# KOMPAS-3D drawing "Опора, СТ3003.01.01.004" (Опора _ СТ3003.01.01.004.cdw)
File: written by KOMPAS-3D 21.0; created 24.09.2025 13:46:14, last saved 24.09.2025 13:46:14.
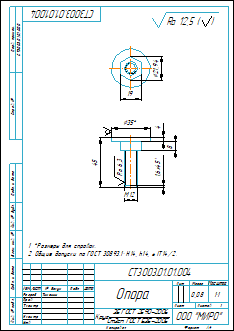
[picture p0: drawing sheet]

Sheet 1: A4, portrait

Document properties: Полное имя файла: C:\Users\1\Yandex.Disk\Документы\Новая папка\Стапель №2\Стапель _ СТ3003.00.00.000\Опора _ СТ3003.01.00.000\2D\Кронштейн _ СТ3003.01.01.000\Опора _ СТ3003.01.01.004.cdw; Знак неуказанной шероховатости: 4; Параметр неуказанной шероховатости: Ra 12,5; Масса: 0.078797

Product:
- Part/product: Опора  | designation СТ3003.01.01.004
    Материал: Круг$d35 ГОСТ 2590-2006;Ст3сп ГОСТ 535-2005$ (density 7850 kg/m3)
    Масса: 0.078797

Title block, sheet 1: Наименование: Опора; designation: СТ3003.01.01.004; Материал: Круг 35 ГОСТ 2590-2006 Ст3сп ГОСТ 535-2005; Масса: 0,08; Количество листов документа: 1; organisation: ООО "МИРО"; Форматы листов документа: A4; Разработал: Тимонин

Views: Вид 1, Спереди, Проекционный вид 2
Referenced files in C:\Users\1\Yandex.Disk\Документы\Новая папка\Стапель №2\Стапель _ СТ3003.00.00.000\Опора _ СТ3003.01.00.000\3D\Кронштейн _ СТ3003.01.01.000\: Опора _ СТ3003.01.01.004.m3d
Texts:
  Ra 6,3
  Ra 12,5
  Ra 12,5 ( )
  СТ3003.01.01.000
  СТ3003.01.01.004 Опора
Dimensions and other numbers on the sheet: 35; 4; 8; 45; 1,6; 12; 19; 21,94; 1:1; 1; 0,08

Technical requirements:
  *Размеры для справок.
  Общие допуски по ГОСТ 30893.1: Н14, h14, ± IT14/2.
